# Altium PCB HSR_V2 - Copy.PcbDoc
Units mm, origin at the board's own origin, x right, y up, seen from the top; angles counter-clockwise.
Board outline 140 x 140 mm, 2 copper layers (Top Layer, Bottom Layer), stack 0.533 mm thick; 53 components, 62 nets, 256 pads, 793 vias.
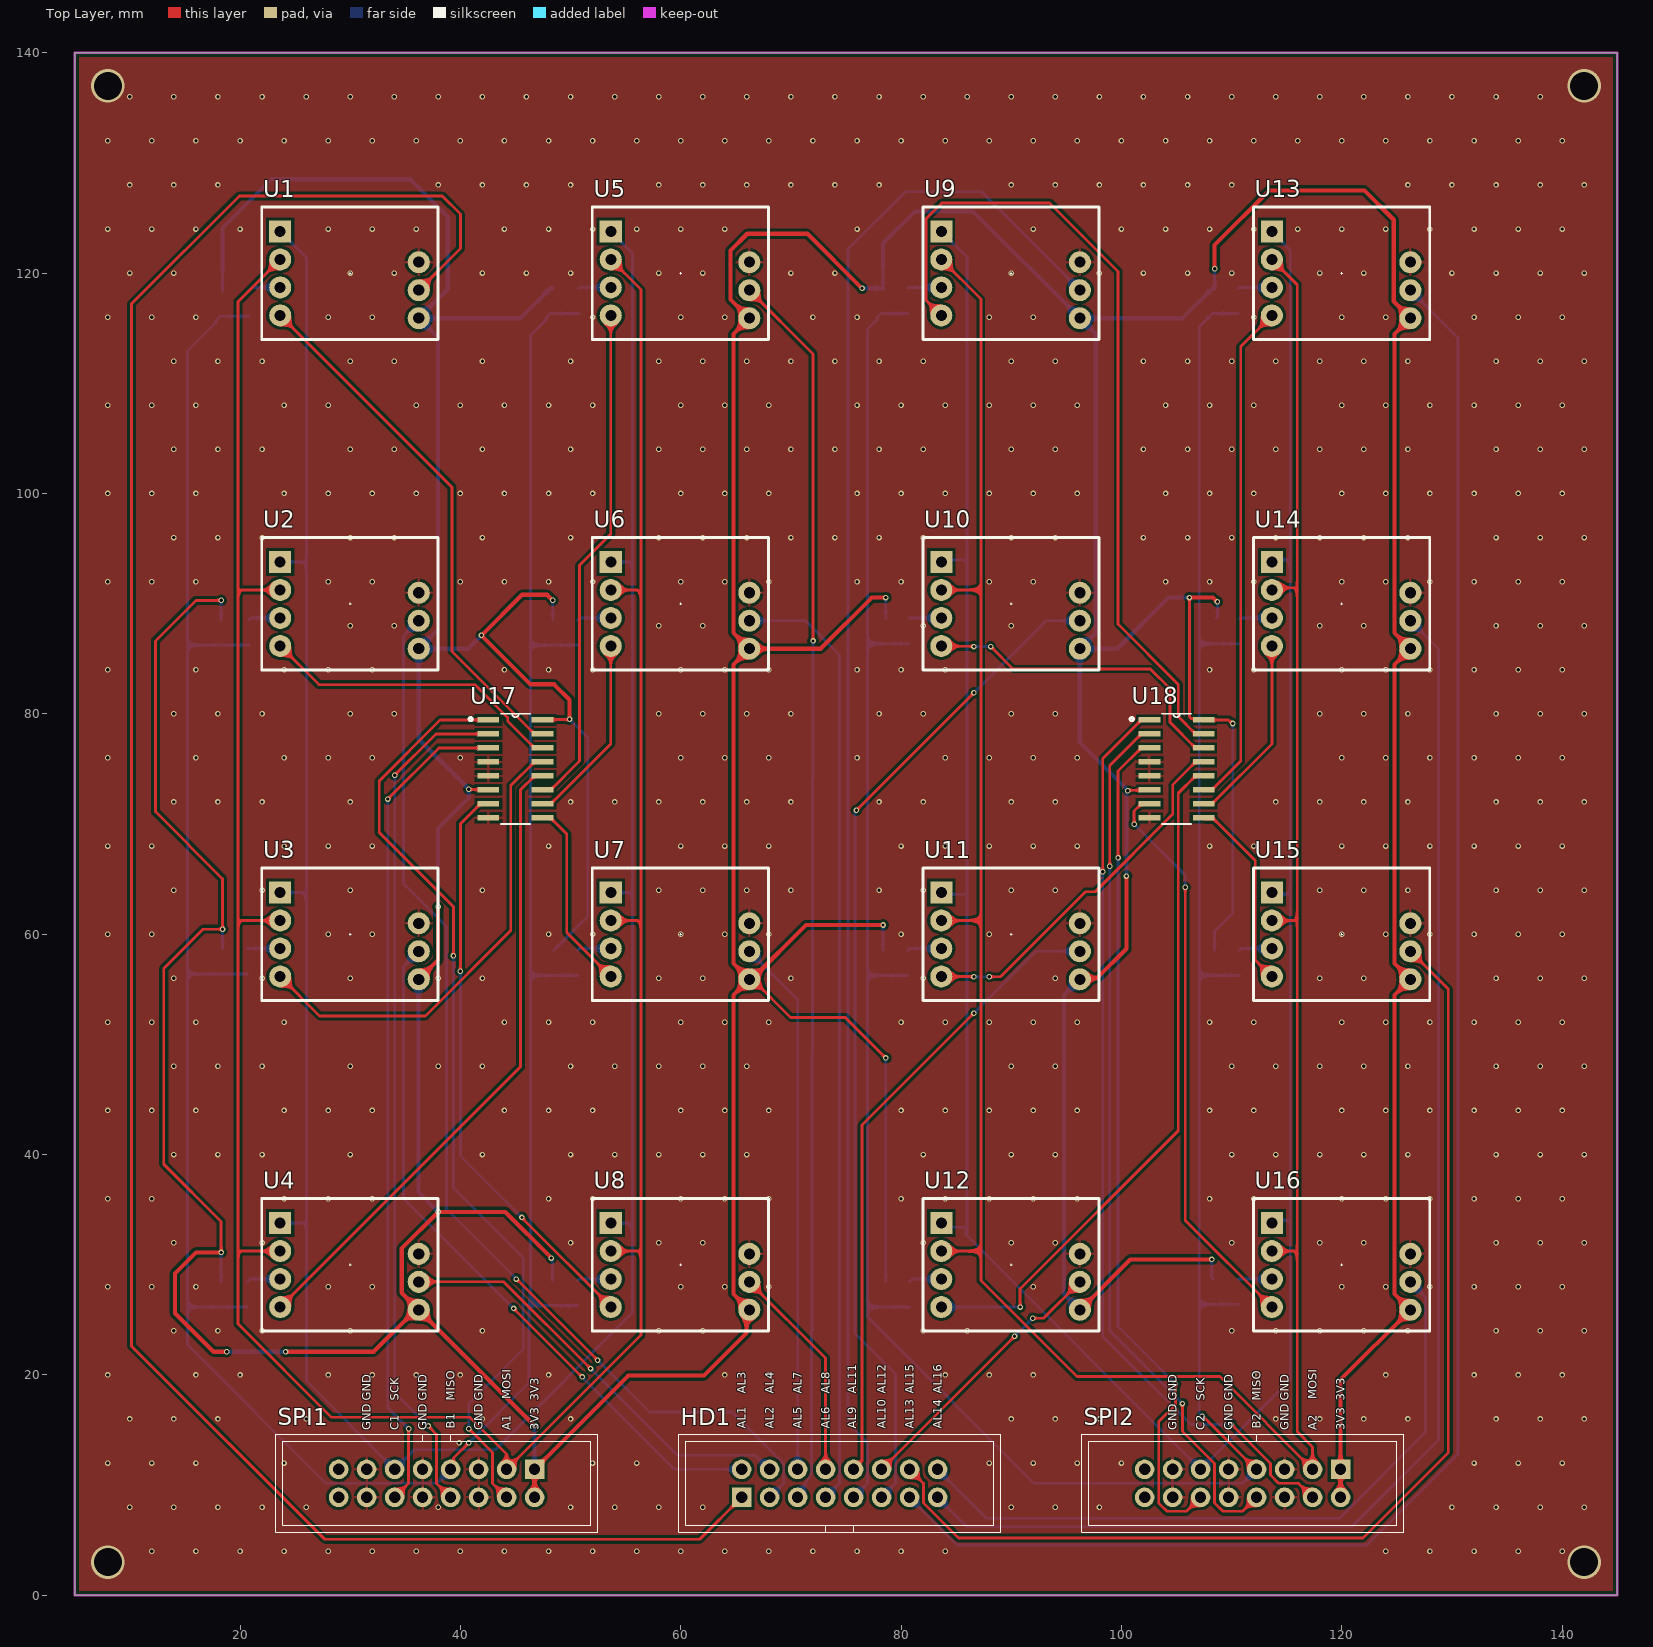
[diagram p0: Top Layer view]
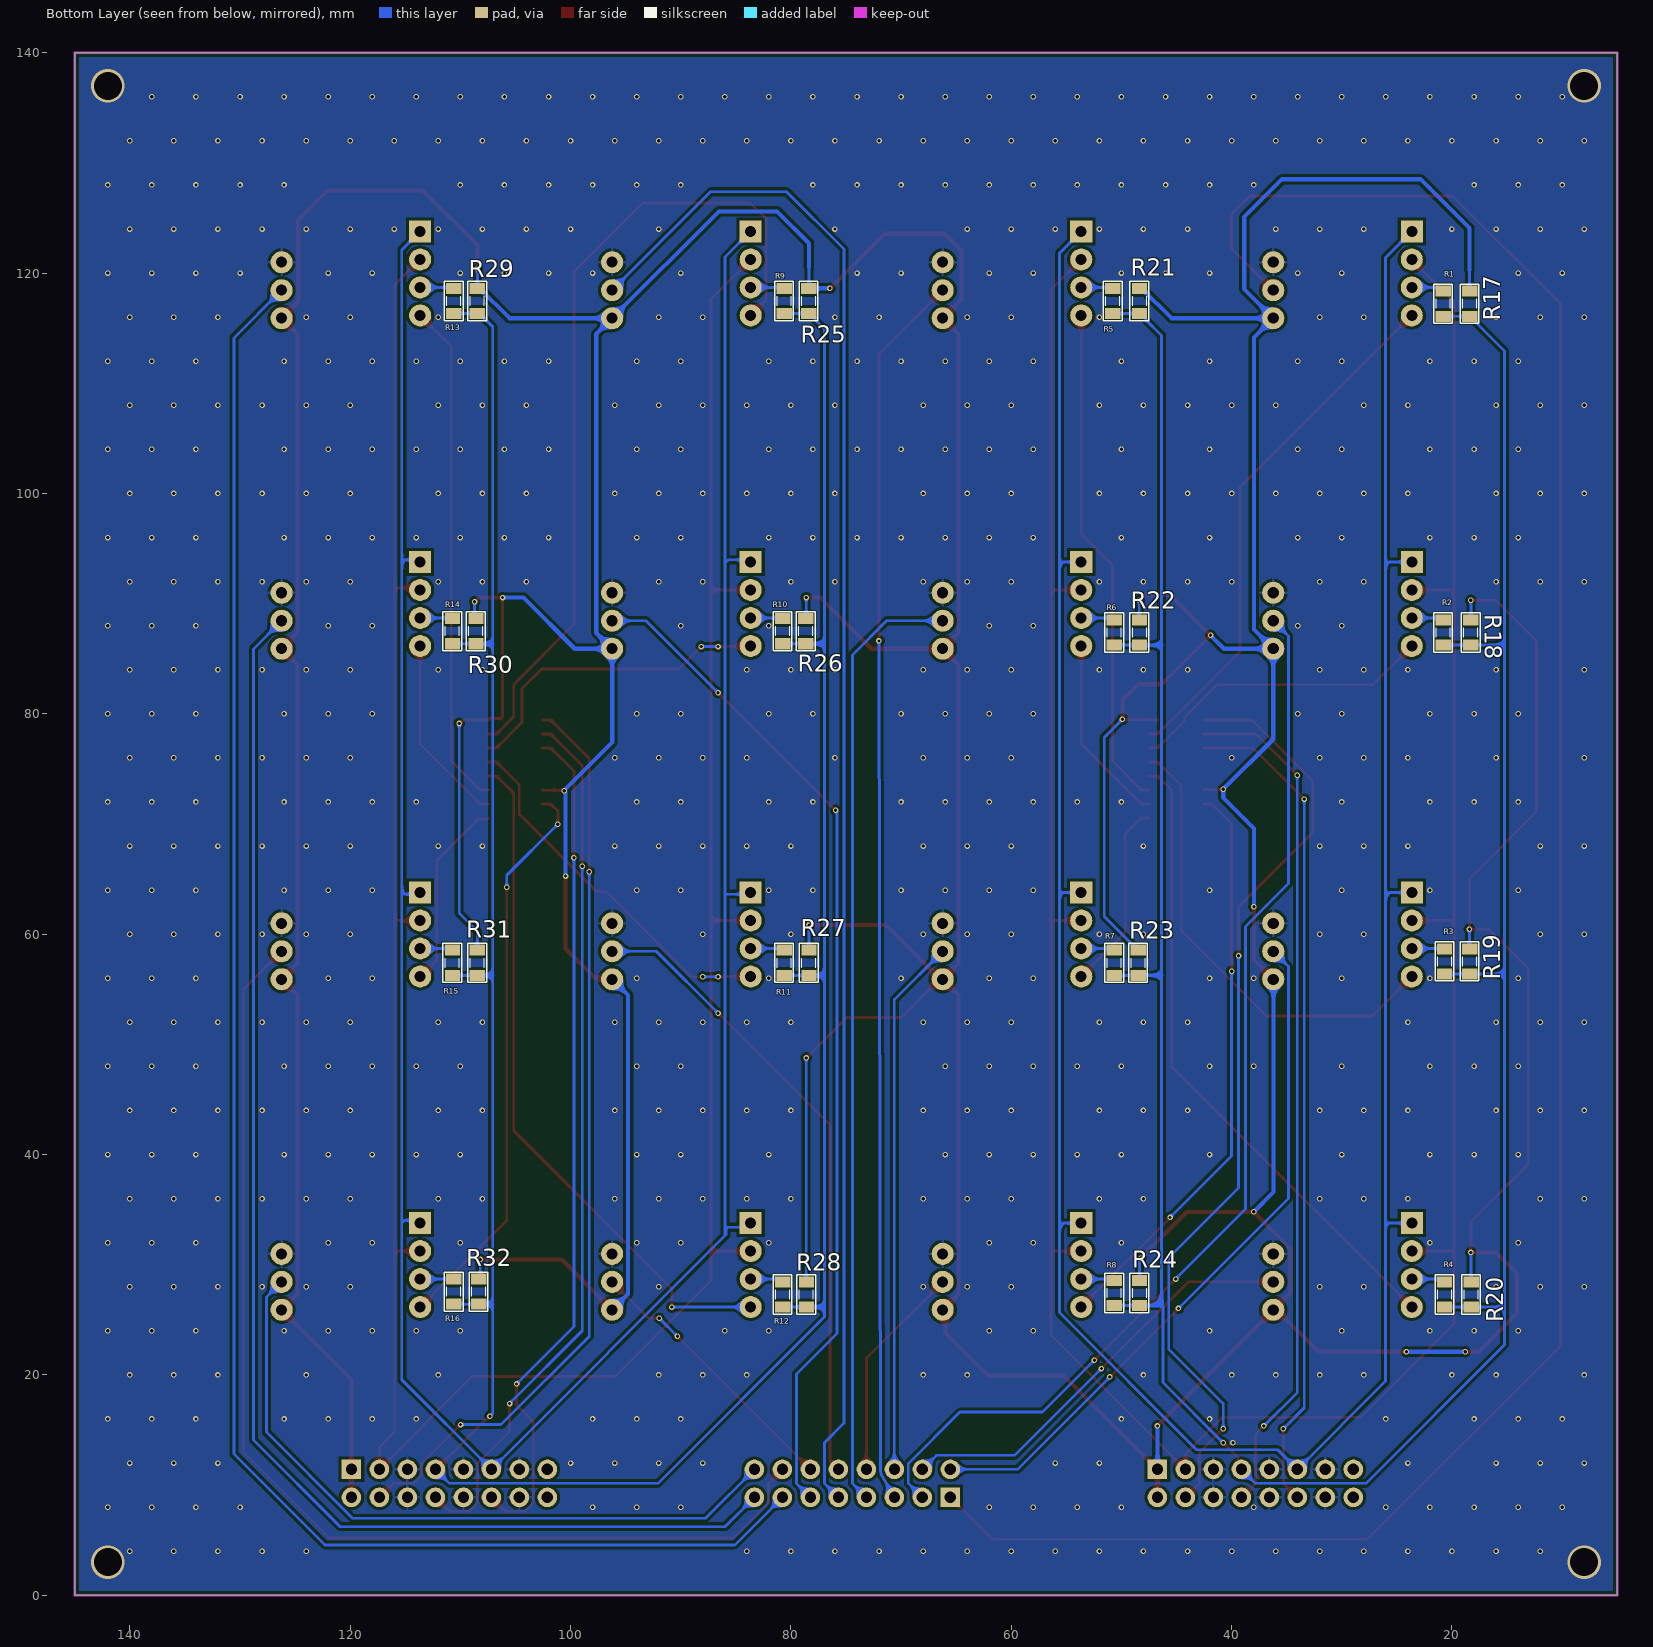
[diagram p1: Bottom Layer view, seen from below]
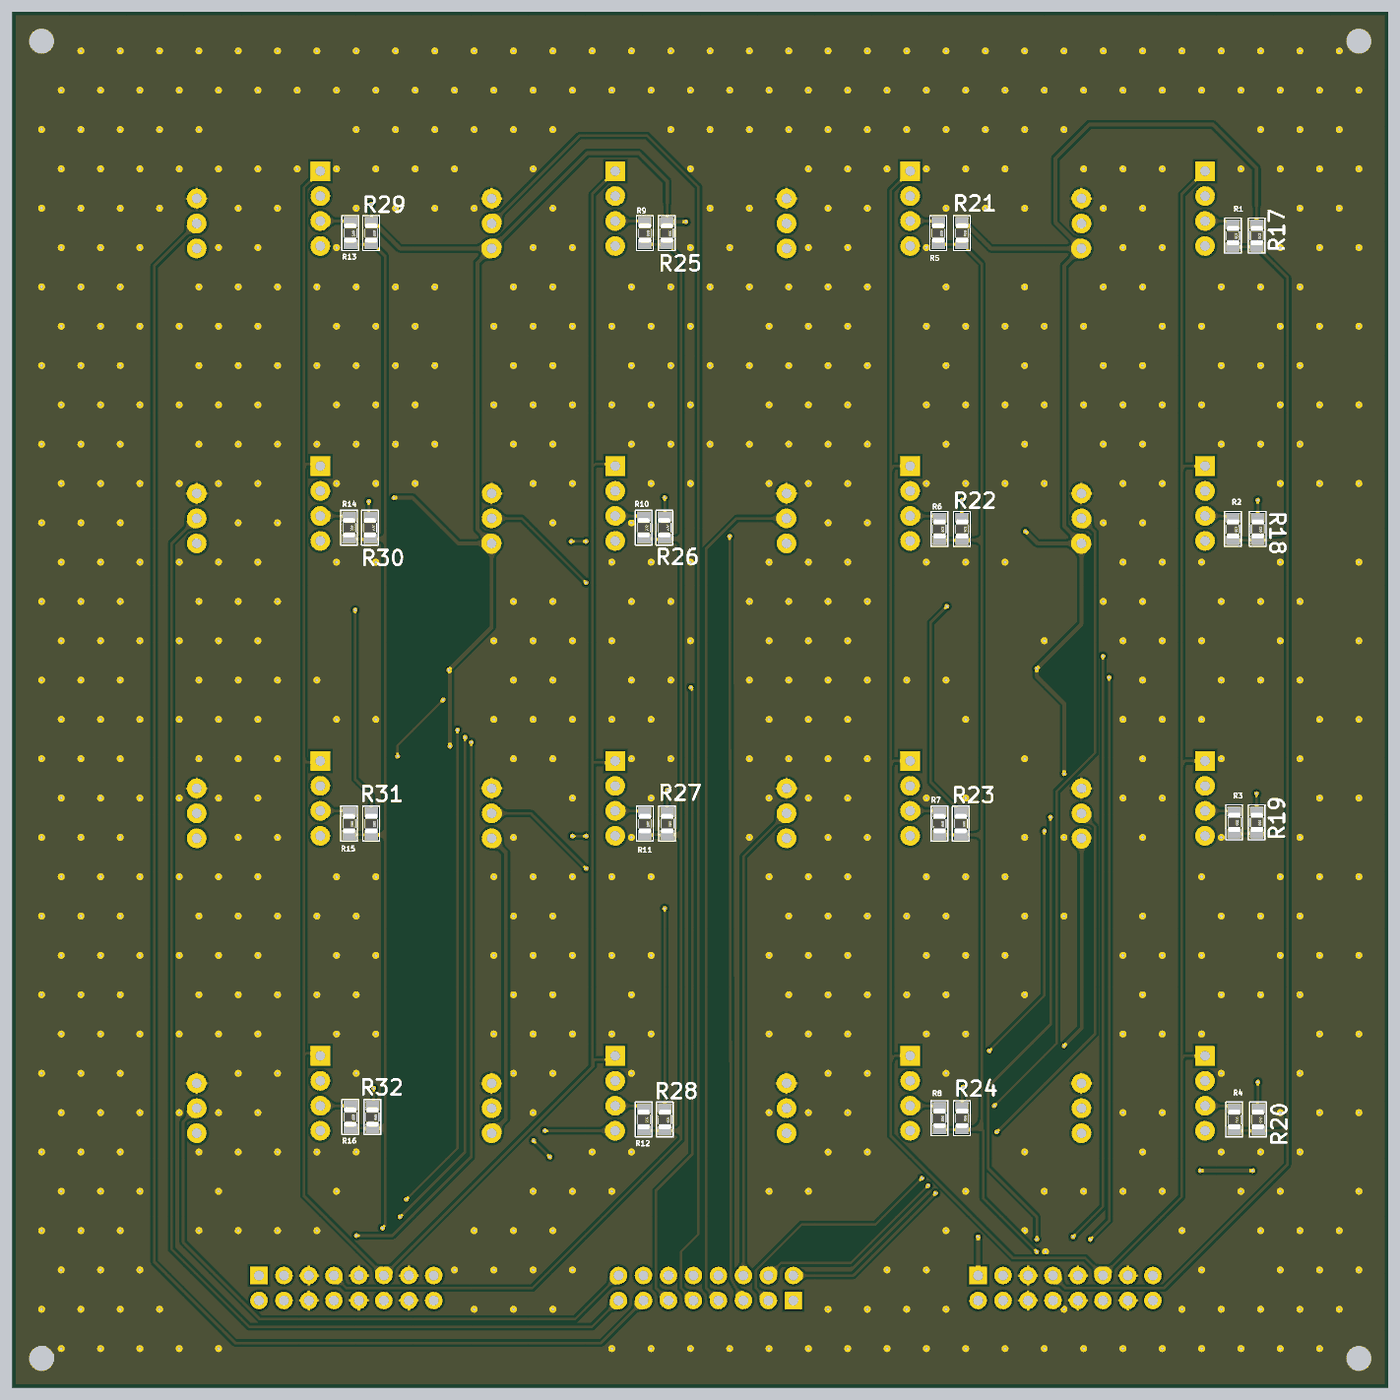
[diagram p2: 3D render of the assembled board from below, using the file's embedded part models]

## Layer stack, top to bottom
Top Solder: solder mask 0.0102, Solder Resist, Dk 3.5
Top Layer: signal copper 0.0356
Dielectric 2: prepreg 0.0711, PP-006, Dk 4.1
Dielectric 1: dielectric 0.32, FR-4, Dk 4.8
Dielectric 3: prepreg 0.0711, PP-006, Dk 4.1
Bottom Layer: signal copper 0.0356
Bottom Solder: solder mask 0.0102, Solder Resist, Dk 3.5

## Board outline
5,0 5,140 145,140 145,0

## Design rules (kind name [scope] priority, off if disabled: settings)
Clearance [All] p1: gap=0.254 ignorepadtopadclearanceinfootprint=FALSE
PolygonConnect [All] p1: connectstyle=Relief reliefconductorwidth=0.254 reliefentries=4 polygonreliefangle="90 Angle" airgapwidth=0.254
RoutingVias [All] p1: holewidth=0.3 width=0.5 viastyle="Through Hole" minholewidth=0.2 minwidth=0.3 maxholewidth=0.711 maxwidth=1.27
SolderMaskExpansion [All] p1: expansion=0.102 istentingtop=FALSE
Width [All] p1: maxlimit=0.762 minlimit=0.254 preferedwidth=0.254 minimp=50.000000 maximp=50.000000 favimp=50.000000
30 further rules are at their usual default settings.

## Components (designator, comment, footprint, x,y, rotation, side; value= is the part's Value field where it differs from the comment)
HD1 "IDC 8X2" IDC16 65.532,8.89 r0 top value="Header 5x2"
R1 "22R" RES-SMD-0805 20.803,117.221 r270 bottom
R2 "22R" RES-SMD-0805 20.803,87.376 r270 bottom
R3 "22R" RES-SMD-0805 20.676,57.531 r270 bottom
R4 "22R" RES-SMD-0805 20.676,27.305 r270 bottom
R5 "22R" RES-SMD-0805 50.775,117.475 r270 bottom
R6 "22R" RES-SMD-0805 50.648,87.376 r270 bottom
R7 "22R" RES-SMD-0805 50.648,57.404 r270 bottom
R8 "22R" RES-SMD-0805 50.648,27.432 r270 bottom
R9 "22R" RES-SMD-0805 80.62,117.475 r270 bottom
R10 "22R" RES-SMD-0805 80.747,87.503 r270 bottom
R11 "22R" RES-SMD-0805 80.62,57.404 r270 bottom
R12 "22R" RES-SMD-0805 80.747,27.305 r270 bottom
R13 "22R" RES-SMD-0805 110.592,117.475 r270 bottom
R14 "22R" RES-SMD-0805 110.719,87.503 r270 bottom
R15 "22R" RES-SMD-0805 110.719,57.404 r270 bottom
R16 "22R" RES-SMD-0805 110.592,27.559 r270 bottom
R17 "10k" RES-SMD-0805 18.39,117.221 r270 bottom
R18 "10k" RES-SMD-0805 18.288,87.376 r270 bottom
R19 "10k" RES-SMD-0805 18.39,57.531 r270 bottom
R20 "10k" RES-SMD-0805 18.263,27.305 r270 bottom
R21 "10k" RES-SMD-0805 48.362,117.475 r270 bottom
R22 "10k" RES-SMD-0805 48.362,87.376 r270 bottom
R23 "10k" RES-SMD-0805 48.489,57.404 r270 bottom
R24 "10k" RES-SMD-0805 48.362,27.432 r270 bottom
R25 "10k" RES-SMD-0805 78.384,117.475 r270 bottom
R26 "10k" RES-SMD-0805 78.638,87.503 r270 bottom
R27 "10k" RES-SMD-0805 78.359,57.404 r270 bottom
R28 "10k" RES-SMD-0805 78.588,27.305 r270 bottom
R29 "10k" RES-SMD-0805 108.458,117.475 r270 bottom
R30 "10k" RES-SMD-0805 108.585,87.503 r270 bottom
R31 "10k" RES-SMD-0805 108.458,57.404 r270 bottom
R32 "10k" RES-SMD-0805 108.331,27.559 r270 bottom
SPI1 "IDC 8X2" IDC16 46.736,11.43 r180 top value="Header 5x2"
SPI2 "IDC 8X2" IDC16 119.888,11.43 r180 top value="Header 5x2"
U1 "TMAG5170_MODULE" "PCBComponent_1 - duplicate" 30,120 r0 top
U2 "TMAG5170_MODULE" "PCBComponent_1 - duplicate" 30,90 r0 top
U3 "TMAG5170_MODULE" "PCBComponent_1 - duplicate" 30,60 r0 top
U4 "TMAG5170_MODULE" "PCBComponent_1 - duplicate" 30,30 r0 top
U5 "TMAG5170_MODULE" "PCBComponent_1 - duplicate" 60,120 r0 top
U6 "TMAG5170_MODULE" "PCBComponent_1 - duplicate" 60,90 r0 top
U7 "TMAG5170_MODULE" "PCBComponent_1 - duplicate" 60,60 r0 top
U8 "TMAG5170_MODULE" "PCBComponent_1 - duplicate" 60,30 r0 top
U9 "TMAG5170_MODULE" "PCBComponent_1 - duplicate" 90,120 r0 top
U10 "TMAG5170_MODULE" "PCBComponent_1 - duplicate" 90,90 r0 top
U11 "TMAG5170_MODULE" "PCBComponent_1 - duplicate" 90,60 r0 top
U12 "TMAG5170_MODULE" "PCBComponent_1 - duplicate" 90,30 r0 top
U13 "TMAG5170_MODULE" "PCBComponent_1 - duplicate" 120,120 r0 top
U14 "TMAG5170_MODULE" "PCBComponent_1 - duplicate" 120,90 r0 top
U15 "TMAG5170_MODULE" "PCBComponent_1 - duplicate" 120,60 r0 top
U16 "TMAG5170_MODULE" "PCBComponent_1 - duplicate" 120,30 r0 top
U17 "SN74LVC138AD" SOIC127P600X175-16N 45,75 r0 top
U18 "SN74LVC138AD" SOIC127P600X175-16N 105,75 r0 top

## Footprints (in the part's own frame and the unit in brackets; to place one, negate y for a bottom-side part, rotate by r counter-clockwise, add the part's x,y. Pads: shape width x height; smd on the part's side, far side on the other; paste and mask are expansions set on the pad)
IDC16 [mil]
  rect 70x70 hole 40: 1(0,0)
  round 70 hole 40: 2(0,100) 3(100,0) 4(100,100) 5(200,0) 6(200,100) 7(300,0) 8(300,100) 9(400,0) 10(400,100) 11(500,0) 12(500,100) 13(600,0) 14(600,100) 15(700,0) 16(700,100)
  silkscreen extent -225,-125 925,225, body extent -225,-125 926,225, height 358
"PCBComponent_1 - duplicate" [mm]
  rect 2x2 hole 1 mask+0.05: 1(-6.35,3.778)
  round 2 hole 1 mask+0.05: 2(-6.35,1.238) 3(-6.35,-1.302) 4(-6.35,-3.842) 5(6.223,-4.092) 6(6.223,-1.552) 7(6.223,0.988)
  silkscreen extent -8.02,-6.03 7.97,6
RES-SMD-0805 [mm]
  rect 1x1.397 smd: 1(-1.143,0) 2(1.143,0)
  silkscreen extent -1.78,-0.86 1.78,0.84, body extent -1,-0.62 1,0.63, height 0.8
SOIC127P600X175-16N [mil]
  rect 78x20 smd: 1(-97,175) 2(-97,125) 3(-97,75) 4(-97,25) 5(-97,-25) 6(-97,-75) 7(-97,-125) 8(-97,-175) 9(97,-175) 10(97,-125) 11(97,-75) 12(97,-25) 13(97,25) 14(97,75) 15(97,125) 16(97,175)
  silkscreen extent -166,-197 52,197, body extent -118,-195 118,195, height 69

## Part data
HD1 SPI1 SPI2: library part "IDC 8x2"
R1 R2 R3 R4 R5 R6 R7 R8 R9 R10 R11 R12 R13 R14 R15 R16 R17 R18 R19 R20 R21 R22 R23 R24 R25 R26 R27 R28 R29 R30 R31 R32: library part "Resistor - SMD", "Resistor SMD", Manufacturer="Generic Components"
U1 U2 U3 U4 U5 U6 U7 U8 U9 U10 U11 U12 U13 U14 U15 U16: "Module TMAG5170 Hall sensor"
U17 U18: "3-Line To 8-Line decoder/Demultiplexer", Package="SOIC-16 Texas Instruments"

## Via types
v1: diameter 0.5, hole 0.3, Top Layer to Bottom Layer, 730 vias
v2: diameter 0.5, hole 0.3, Top Layer to Bottom Layer, tented top, 59 vias
v3: diameter 3.048, hole 2.54, Top Layer to Bottom Layer, tented top, 4 vias

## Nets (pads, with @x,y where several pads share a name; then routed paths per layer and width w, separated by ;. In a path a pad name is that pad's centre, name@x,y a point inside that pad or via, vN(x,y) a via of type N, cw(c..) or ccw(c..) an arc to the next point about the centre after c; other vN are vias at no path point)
3V3: R17.1 R18.1 R19.1 R20.1 R21.1 R22.1 R23.1 R24.1 R25.1 R26.1 R27.1 R28.1 R29.1 R30.1 R31.1 R32.1 SPI1.1 SPI1.2 SPI2.1 SPI2.2 U1.5 U2.5 U3.5 U4.5 U5.5 U6.5 U7.5 U8.5 U9.5 U10.5 U11.5 U12.5 U13.5 U14.5 U15.5 U16.5 U17.6 U17.16 U18.6 U18.16 | length 918.7
  Top Layer w0.254: v2(18.288,31.115) 18.288,33.909 13.081,39.116 13.081,56.896 16.637,60.452 v2(18.415,60.452) 18.415,65.024 12.319,71.12 12.319,86.614 16.002,90.297 v2(18.288,90.297) ; v2(40.767,73.152) 40.795,73.124 42.508,73.124 U17.6 ; U17.16@46.727,79.445 U17.16 47.492,79.474 49.883,79.474 v2(49.911,79.502) ; U7.5@66.52,55.908 69.977,52.451 74.93,52.451 v2(78.613,48.768) ; v2(100.584,73.025) 100.619,73.06 102.501,73.06 U18.6 ; v2(106.172,90.551) 106.172,79.721 106.321,79.572 107.337,79.572 U18.16 109.718,79.445 110.042,79.121 v2(110.109,79.121)
  Top Layer w0.381: v2(18.288,31.115) 16.002,31.115 14.097,29.21 14.097,25.59 17.59,22.098 v2(18.796,22.098) ; v2(24.13,22.098) 32.131,22.098 35.941,25.908 U4.5 ; U3.5 37.973,57.657 v2(37.973,62.484) ; SPI1.2 SPI1.1 55.245,19.939 62.103,19.939 65.973,23.809 65.973,25.657 U8.5 64.779,27.352 64.779,54.463 U7.5 ; v2(46.736,15.367) 46.736,15.381 36.223,25.894 U4.5 ; v2(48.26,30.607) 44.069,34.798 v2(37.991,34.798) 34.671,31.478 34.671,27.46 U4.5 ; v2(48.387,90.297) 47.879,90.805 45.593,90.805 v2(41.91,87.122) 46.355,82.677 48.514,82.677 49.911,81.28 v2(49.911,79.502) ; v2(76.454,118.618) 71.501,123.571 66.04,123.571 64.516,122.047 64.516,117.615 U5.5 64.779,114.463 64.779,87.352 U6.5 ; v2(78.359,60.833) 71.374,60.833 66.449,55.908 U7.5 ; v2(78.613,90.551) 77.343,90.551 72.7,85.908 U6.5 ; U12.5 100.796,30.48 v2(108.204,30.48) ; U11.5 96.328,56.012 97.795,56.012 100.457,58.674 v2(100.457,65.278) ; v2(106.172,90.551) 108.299,90.551 108.68,90.17 v2(108.712,90.17) ; v2(108.458,120.396) 108.458,122.555 113.411,127.508 122.047,127.508 124.714,124.841 124.714,117.417 U13.5 124.779,114.463 124.779,87.352 U14.5 124.779,84.463 124.779,57.352 U15.5 124.779,54.463 124.779,27.352 U16.5 119.888,19.572 SPI2.1 SPI2.2 ; U7.5 64.779,57.352 64.779,84.463 U6.5
  Bottom Layer w0.254: R20.1 18.288,28.473 v2(18.288,31.115) ; R18.1 v2(18.288,90.297) ; R19.1 18.415,58.699 v2(18.415,60.452) ; R17.1 18.415,118.389 18.415,120.269 ; R24.1 v2@48.362,30.439 ; R22.1 48.387,88.544 v2(48.387,90.297) ; R21.1 R21.1@48.387,118.643 ; R23.1 51.562,61.62 51.562,77.851 v2(49.911,79.502) ; R27.1 v2(78.359,60.833) ; 78.359,120.523 78.359,118.643 R25.1 ; R28.1 78.613,28.473 v2(78.613,48.768) ; v2(78.613,90.551) 78.613,88.671 R26.1 ; v2(108.204,30.48) 108.204,28.829 R32.1 ; R31.1 108.458,60.258 110.109,61.909 v2(110.109,79.121) ; R29.1 v2(108.458,120.396) ; R30.1 108.712,88.773 v2(108.712,90.17)
  Bottom Layer w0.381: 18.415,120.269 18.415,124.079 22.86,128.524 35.433,128.524 38.862,125.095 38.862,118.546 U1.5 ; v2(18.796,22.098) v2(24.13,22.098) ; U3.5 36.195,55.879 36.195,36.594 v2(37.991,34.798) ; v2(37.973,62.484) 37.973,69.596 40.767,72.39 v2(40.767,73.152) 36.223,77.696 U2.5 ; v2(41.91,87.122) 40.696,85.908 U2.5 ; SPI1.1 v2(46.736,15.367) ; R21.1 48.163,118.618 45.453,115.908 U1.5 ; v2(76.454,118.618) R25.1 ; 78.359,120.523 78.359,122.713 81.249,125.603 86.528,125.603 U9.5 ; U12.5 94.779,27.352 94.779,54.463 U11.5 ; v2(100.457,65.278) 100.457,72.866 100.584,72.993 v2(100.584,73.025) 96.223,77.386 U10.5 ; v2(106.172,90.551) 104.267,90.551 99.624,85.908 U10.5 ; R29.1 108.26,118.618 105.549,115.908 U9.5 ; U2.5 37.973,87.657 37.973,114.158 U1.5 ; U10.5 97.668,87.352 97.668,114.463 U9.5
A1: SPI1.4 U17.1 | length 86.1
  Top Layer w0.254: v2(39.37,58.039) 39.37,62.484 32.639,69.215 32.639,73.917 38.167,79.445 U17.1 ; v2(40.767,15.113) 42.926,12.954 42.926,10.16 SPI1.4
  Bottom Layer w0.254: v2(39.37,58.039) 39.37,36.957 45.716,30.611 45.716,22.348 40.767,17.399 v2(40.767,15.113)
A2: SPI2.4 U18.1 | length 83.9
  Top Layer w0.254: v2(98.298,65.659) 98.298,75.943 101.8,79.445 U18.1 ; v2(109.982,15.494) 110,15.494 113.538,11.956 113.538,10.904 114.282,10.16 115.334,10.16 116.078,10.16 SPI2.4
  Bottom Layer w0.254: v2(98.298,65.659) 98.298,23.495 106.299,15.494 v2(109.982,15.494)
AL1: HD1.1 U1.6 | length 201.9
  Top Layer w0.254: U1.6 40.005,122.229 40.005,125.349 38.354,127 19.939,127 10.16,117.221 10.16,22.606 27.686,5.08 61.722,5.08 HD1.1
AL2: HD1.3 U2.6 | length 99.3
  Top Layer w0.254: v2(45.085,28.702) v2(52.451,21.336)
  Bottom Layer w0.254: U2.6 34.842,87.067 34.842,64.599 38.735,60.706 38.735,35.052 v2(45.085,28.702) ; v2(52.451,21.336) 57.164,16.623 64.676,16.623 69.342,11.956 69.342,10.16 HD1.3
AL3: HD1.2 U3.6 | length 63.9
  Top Layer w0.254: v2(44.831,26.035) v2(51.054,19.812)
  Bottom Layer w0.254: U3.6 34.842,57.067 34.842,36.024 v2(44.831,26.035) ; v2(51.054,19.812) 59.436,11.43 HD1.2
AL4: HD1.4 U4.6 | length 38.9
  Top Layer w0.254: U4.6 43.942,28.448 v2(51.816,20.574)
  Bottom Layer w0.254: v2(51.816,20.574) 59.69,12.7 66.802,12.7 HD1.4
AL5: HD1.5 U5.6 | length 112.3
  Top Layer w0.254: U5.6 72.009,112.662 v2(72.009,86.614)
  Bottom Layer w0.254: HD1.5 71.712,10.795 ccw(c70.612,11.43) 71.882,11.432 v2(72.009,86.614)
AL6: HD1.7 U6.6 | length 86.5
  Bottom Layer w0.254: U6.6 71.318,88.448 74.422,85.344 74.422,10.16 HD1.7
AL7: HD1.6 U7.6 | length 48.8
  Bottom Layer w0.254: U7.6 70.612,54.059 HD1.6
AL8: HD1.8 U8.6 | length 19.9
  Top Layer w0.254: U8.6 73.152,21.519 HD1.8
AL9: HD1.9 U9.6 | length 141.4
  Bottom Layer w0.254: HD1.9 76.962,10.16 76.962,13.843 75.184,15.621 75.184,122.174 80.391,127.381 87.29,127.381 U9.6
AL10: HD1.11 U10.6 | length 91.9
  Top Layer w0.254: v2(75.946,71.247) 86.61,81.911 v2(86.61,81.915)
  Bottom Layer w0.254: v2(75.946,71.247) 75.946,71.18 75.819,71.053 75.819,23.749 79.502,20.066 79.502,10.16 HD1.11 ; v2(86.61,81.915) 93.143,88.448 U10.6
AL11: HD1.10 U11.6 | length 57.9
  Top Layer w0.254: HD1.10 75.692,11.492 76.454,12.254 76.454,42.676 v2(86.61,52.832)
  Bottom Layer w0.254: v2(86.61,52.832) 92.226,58.448 U11.6
AL12: HD1.12 U12.6 | length 25
  Top Layer w0.254: HD1.12 v2(90.297,23.495) ; v2(91.948,25.146) 92.922,25.146 U12.6
  Bottom Layer w0.254: v2(90.297,23.495) v2(91.948,25.146)
AL13: HD1.13 U13.6 | length 162.4
  Bottom Layer w0.254: HD1.13 85.09,4.572 122.301,4.572 130.556,12.827 130.556,114.115 U13.6
AL14: HD1.15 U14.6 | length 125.2
  Bottom Layer w0.254: HD1.15 85.979,6.223 120.904,6.223 128.778,14.097 128.778,85.893 U14.6
AL15: HD1.14 U15.6 | length 102.7
  Top Layer w0.254: HD1.14 82.042,10.16 82.042,8.364 85.199,5.207 121.92,5.207 129.667,12.954 129.667,55.004 U15.6
AL16: HD1.16 U16.6 | length 63.6
  Bottom Layer w0.254: HD1.16 87.757,6.985 119.779,6.985 127.604,14.81 127.604,27.067 U16.6
B1: SPI1.8 U17.2 | length 77.7
  Top Layer w0.254: v2(34.036,74.422) 37.789,78.175 U17.2 ; v2(37.084,15.367) 37.846,14.605 37.846,10.16 SPI1.8
  Bottom Layer w0.254: v2(34.036,74.422) 34.036,18.415 v2(37.084,15.367)
B2: SPI2.8 U18.2 | length 80.3
  Top Layer w0.254: v2(98.933,66.167) 98.933,75.308 101.8,78.175 U18.2 ; v2(105.537,17.399) 105.537,14.877 108.458,11.956 108.458,8.364 109.202,7.62 110.998,7.62 SPI2.8
  Bottom Layer w0.254: v2(98.933,66.167) 98.933,24.003 v2(105.537,17.399)
C1: SPI1.12 U17.3 | length 75.7
  Top Layer w0.254: v2(33.405,72.263) 38.047,76.905 U17.3 ; SPI1.12 35.306,10.16 v2(35.306,15.113)
  Bottom Layer w0.254: v2(33.405,72.263) 33.405,17.014 v2(35.306,15.113)
C2: SPI2.12 U18.3 | length 77.6
  Top Layer w0.254: v2(99.695,66.929) 99.695,74.8 101.8,76.905 U18.3 ; v2(104.902,19.177) 104.902,17.272 103.378,15.748 103.378,11.437 ; SPI2.12 105.918,7.62 104.122,7.62 103.452,8.29 103.378,8.364 103.378,8.883 ; 103.378,8.883 cw(c104.648,8.89) 103.378,8.897 ; 103.378,8.883 cw(c104.648,8.89) 103.378,8.897 ; 103.378,8.897 103.378,11.423 ; 103.378,11.423 cw(c104.648,11.43) 103.378,11.437 ; 103.378,11.423 cw(c104.648,11.43) 103.378,11.437
  Bottom Layer w0.254: v2(99.695,66.929) 99.695,24.384 v2(104.902,19.177)
GND: SPI1.5 SPI1.6 SPI1.9 SPI1.10 SPI1.13 SPI1.14 SPI2.5 SPI2.6 SPI2.9 SPI2.10 SPI2.13 SPI2.14 U1.7 U2.7 U3.7 U4.7 U5.7 U6.7 U7.7 U8.7 U9.7 U10.7 U11.7 U12.7 U13.7 U14.7 U15.7 U16.7 U17.4 U17.5 U17.8 U18.4 U18.5 U18.8
  other v1: 12,4 16,4 20,4 24,4 28,4 32,4 36,4 40,4 44,4 48,4 52,4 56,4 60,4 64,4 68,4 72,4 76,4 80,4 84,4 124,4 128,4 132,4 136,4 140,4 10,8 14,8 18,8 22,8 26,8 38,8 50,8 54,8 58,8 62,8 90,8 94,8 98,8 130,8 134,8 138,8 142,8 8,12 12,12 16,12 24,12 52,12 56,12 88,12 92,12 96,12 100,12 132,12 136,12 140,12 10,16 14,16 18,16 26,16 42,16 50,16 90,16 94,16 98,16 114,16 118,16 122,16 126,16 134,16 138,16 142,16 8,20 16,20 20,20 28,20 32,20 36,20 40,20 48,20 64,20 68,20 84,20 88,20 92,20 112,20 124,20 132,20 136,20 140,20 14,24 18,24 22,24 30,24 42,24 58,24 62,24 82,24 86,24 110,24 114,24 118,24 122,24 126,24 134,24 138,24 142,24 8,28 12,28 16,28 28,28 32,28 60,28 64,28 68,28 92,28 120,28 124,28 128,28 132,28 136,28 140,28 14,32 22,32 50,32 58,32 62,32 82,32 90,32 94,32 110,32 118,32 122,32 134,32 138,32 142,32 8,36 12,36 24,36 28,36 32,36 48,36 52,36 60,36 64,36 68,36 80,36 84,36 88,36 92,36 96,36 108,36 112,36 120,36 124,36 128,36 132,36 136,36 140,36 14,40 18,40 22,40 30,40 42,40 50,40 54,40 58,40 62,40 66,40 82,40 90,40 94,40 110,40 114,40 118,40 122,40 126,40 134,40 138,40 142,40 8,44 12,44 16,44 24,44 28,44 32,44 44,44 48,44 52,44 60,44 64,44 68,44 80,44 84,44 88,44 92,44 96,44 108,44 112,44 120,44 124,44 128,44 132,44 136,44 140,44 14,48 18,48 22,48 30,48 38,48 42,48 50,48 54,48 58,48 62,48 66,48 90,48 94,48 110,48 114,48 118,48 122,48 126,48 134,48 138,48 142,48 8,52 12,52 16,52 24,52 44,52 48,52 52,52 60,52 64,52 68,52 80,52 84,52 88,52 92,52 96,52 108,52 112,52 120,52 124,52 128,52 132,52 136,52 140,52 14,56 22,56 30,56 38,56 42,56 58,56 62,56 70,56 82,56 94,56 118,56 122,56 134,56 138,56 142,56 8,60 12,60 28,60 32,60 48,60 52,60 60,60 64,60 68,60 80,60 88,60 120,60 124,60 128,60 132,60 136,60 140,60 14,64 22,64 30,64 42,64 58,64 62,64 66,64 70,64 78,64 82,64 90,64 94,64 118,64 122,64 126,64 134,64 138,64 142,64 8,68 12,68 24,68 28,68 32,68 48,68 60,68 64,68 68,68 80,68 84,68 88,68 92,68 96,68 108,68 112,68 120,68 124,68 128,68 132,68 136,68 140,68 14,72 18,72 22,72 30,72 50,72 54,72 58,72 62,72 66,72 70,72 78,72 82,72 90,72 94,72 114,72 118,72 122,72 126,72 134,72 138,72 142,72 8,76 16,76 24,76 28,76 32,76 40,76 60,76 64,76 68,76 76,76 84,76 88,76 92,76 96,76 120,76 124,76 128,76 132,76 136,76 140,76 14,80 18,80 22,80 30,80 34,80 58,80 62,80 66,80 70,80 78,80 82,80 90,80 94,80 118,80 122,80 126,80 134,80 138,80 142,80 8,84 16,84 24,84 28,84 32,84 44,84 48,84 52,84 60,84 64,84 68,84 76,84 80,84 84,84 108,84 112,84 120,84 124,84 128,84 132,84 136,84 140,84 30,88 34,88 58,88 62,88 82,88 90,88 118,88 122,88 134,88 138,88 142,88 8,92 12,92 16,92 28,92 32,92 40,92 44,92 48,92 52,92 60,92 64,92 68,92 76,92 80,92 88,92 92,92 104,92 108,92 112,92 120,92 124,92 128,92 132,92 136,92 140,92 14,96 18,96 22,96 30,96 34,96 42,96 50,96 58,96 62,96 66,96 70,96 74,96 78,96 82,96 90,96 94,96 102,96 106,96 110,96 114,96 118,96 122,96 126,96 134,96 138,96 142,96 8,100 12,100 16,100 24,100 28,100 32,100 36,100 40,100 44,100 48,100 52,100 60,100 64,100 68,100 76,100 80,100 84,100 88,100 92,100 96,100 104,100 108,100 112,100 120,100 124,100 128,100 132,100 136,100 140,100 14,104 18,104 22,104 30,104 34,104 42,104 50,104 58,104 62,104 66,104 70,104 74,104 78,104 82,104 90,104 94,104 102,104 106,104 110,104 114,104 118,104 122,104 126,104 134,104 138,104 142,104 8,108 12,108 16,108 24,108 28,108 36,108 40,108 44,108 48,108 52,108 60,108 64,108 68,108 76,108 80,108 84,108 88,108 92,108 96,108 104,108 108,108 112,108 120,108 124,108 128,108 132,108 136,108 140,108 14,112 18,112 22,112 30,112 34,112 42,112 50,112 58,112 62,112 66,112 70,112 74,112 78,112 82,112 90,112 94,112 102,112 106,112 110,112 114,112 118,112 122,112 126,112 134,112 138,112 142,112 8,116 12,116 16,116 28,116 32,116 52,116 60,116 64,116 72,116 76,116 88,116 92,116 112,116 120,116 124,116 132,116 136,116 140,116 10,120 14,120 30,120 34,120 42,120 46,120 50,120 58,120 62,120 70,120 74,120 90,120 98,120 102,120 106,120 110,120 118,120 122,120 130,120 134,120 138,120 142,120 8,124 12,124 16,124 20,124 28,124 32,124 36,124 44,124 48,124 52,124 56,124 60,124 64,124 76,124 92,124 100,124 104,124 108,124 112,124 116,124 120,124 124,124 128,124 132,124 136,124 140,124 10,128 14,128 18,128 38,128 42,128 46,128 50,128 54,128 58,128 62,128 66,128 70,128 74,128 78,128 90,128 94,128 98,128 102,128 106,128 110,128 126,128 130,128 134,128 138,128 142,128 8,132 12,132 16,132 20,132 24,132 28,132 32,132 36,132 40,132 44,132 48,132 52,132 56,132 60,132 64,132 68,132 72,132 76,132 80,132 84,132 88,132 92,132 96,132 100,132 104,132 108,132 112,132 116,132 120,132 124,132 128,132 132,132 136,132 140,132 10,136 14,136 18,136 22,136 26,136 30,136 34,136 38,136 42,136 46,136 50,136 54,136 58,136 62,136 66,136 70,136 74,136 78,136 82,136 86,136 90,136 94,136 98,136 102,136 106,136 110,136 114,136 118,136 122,136 126,136 130,136 134,136 138,136
  other v2: 39.878,13.847
  other v3: 8,3 142,3 8,137 142,137
NetR1_1: R1.1 U1.3 | length 3
  Bottom Layer w0.254: R1.1 21.136,118.698 U1.3
NetR2_1: R2.1 U2.3 | length 2.9
  Bottom Layer w0.254: R2.1 20.981,88.698 U2.3
NetR3_1: R3.1 U3.3 | length 3
  Bottom Layer w0.254: R3.1 20.699,58.698 U3.3
NetR4_1: R4.1 U4.3 | length 3.1
  Bottom Layer w0.254: R4.1 20.925,28.698 U4.3
NetR5_1: R5.1 U5.3 | length 2.9
  Bottom Layer w0.254: R5.1 50.854,118.698 U5.3
NetR6_1: R6.1 U6.3 | length 3.1
  Bottom Layer w0.254: R6.1 50.826,88.698 U6.3
NetR7_1: R7.1 U7.3 | length 3.1
  Bottom Layer w0.254: R7.1 50.798,58.698 U7.3
NetR8_1: R8.1 U8.3 | length 3.1
  Top Layer w0.254: U8.3@53.648,28.7 U8.3
  Bottom Layer w0.254: R8.1 50.77,28.698 U8.3
NetR9_1: R9.1 U9.3 | length 3.1
  Top Layer w0.254: U9.3@83.627,118.721 U9.3
  Bottom Layer w0.254: R9.1 80.699,118.698 U9.3
NetR10_1: R10.1 U10.3 | length 3
  Top Layer w0.254: U10.3@83.624,88.672 U10.3
  Bottom Layer w0.254: R10.1 80.798,88.698 U10.3
NetR11_1: R11.1 U11.3 | length 3.1
  Bottom Layer w0.254: R11.1 80.77,58.698 U11.3
NetR12_1: R12.1 U12.3 | length 3
  Bottom Layer w0.254: R12.1 80.996,28.698 U12.3
NetR13_1: R13.1 U13.3 | length 3.1
  Top Layer w0.254: U13.3@113.61,118.658 U13.3
  Bottom Layer w0.254: R13.1 110.671,118.698 U13.3
NetR14_1: R14.1 U14.3 | length 3
  Top Layer w0.254: U14.3@113.613,88.735 U14.3
  Bottom Layer w0.254: R14.1 110.77,88.698 U14.3
NetR15_1: R15.1 U15.3 | length 3
  Top Layer w0.254: U15.3@113.638,58.686 U15.3
  Bottom Layer w0.254: R15.1 110.869,58.698 U15.3
NetR16_1: R16.1 U16.3 | length 3.1
  Bottom Layer w0.254: R16.1 110.596,28.698 U16.3
SENS1: U1.4 U17.15 | length 48.3
  Top Layer w0.254: U1.4 39.243,100.565 39.243,85.659 46.727,78.175 U17.15
SENS2: U2.4 U17.14 | length 27.8
  Top Layer w0.254: U2.4 27.161,82.647 41.305,82.647 44.294,79.658 44.294,79.338 46.727,76.905 U17.14
SENS3: U3.4 U17.13 | length 42.6
  Top Layer w0.254: U3.4 27.23,52.578 36.83,52.578 44.577,60.325 44.577,73.485 46.727,75.635 U17.13
SENS4: U4.4 U17.12 | length 58.5
  Top Layer w0.254: U4.4 45.466,47.973 45.466,73.104 46.727,74.365 U17.12
SENS5: U5.4 U17.11 | length 46.1
  Top Layer w0.254: U17.11 48.2,73.095 50.822,75.716 50.822,93.488 53.65,96.317 U5.4
SENS6: U6.4 U17.10 | length 17.3
  Top Layer w0.254: U17.10 48.2,71.825 53.65,77.275 U6.4
SENS7: U7.4 U17.9 | length 17.4
  Top Layer w0.254: U17.9 48.2,70.555 49.657,69.098 49.657,60.151 U7.4
SENS8: U8.4 U17.7 | length 52.8
  Top Layer w0.254: v2(40.001,56.642) 40.001,70.026 41.8,71.825 U17.7 ; v2(45.593,34.29) 45.593,34.253 53.65,26.195 U8.4
  Bottom Layer w0.254: v2(40.001,56.642) 40.001,39.882 v2(45.593,34.29)
SENS9: U9.4 U18.15 | length 75.6
  Top Layer w0.254: U9.4 82.269,117.539 82.269,124.936 83.699,126.365 93.472,126.365 99.695,120.142 99.695,88.138 105.156,82.677 105.156,79.746 106.727,78.175 U18.15
SENS10: U10.4 U18.14 | length 29.4
  Top Layer w0.254: U10.4 83.676,86.132 86.588,86.132 v2(86.614,86.106) ; v2(88.138,86.106) 90.17,84.074 102.616,84.074 104.394,82.296 104.394,79.238 106.727,76.905 U18.14
  Bottom Layer w0.254: v2(86.614,86.106) v2(88.138,86.106)
SENS11: U11.4 U18.13 | length 33.5
  Top Layer w0.254: U11.4 83.656,56.152 86.592,56.152 v2(86.61,56.134) ; v2(88.011,56.134) 89.027,56.134 96.746,63.853 97.618,63.853 104.648,70.883 104.648,73.556 106.727,75.635 U18.13
  Bottom Layer w0.254: v2(86.61,56.134) v2(88.011,56.134)
SENS12: U12.4 U18.12 | length 62.7
  Top Layer w0.254: v2(90.805,26.162) 90.805,27.813 105.156,42.164 105.156,72.794 106.727,74.365 U18.12
  Bottom Layer w0.254: U12.4 83.652,26.16 90.803,26.16 v2(90.805,26.162)
SENS13: U13.4 U18.11 | length 46.1
  Top Layer w0.254: U18.11 108.2,73.095 110.822,75.716 110.822,113.329 U13.4
SENS14: U14.4 U18.10 | length 17.3
  Top Layer w0.254: U18.10 108.2,71.825 113.65,77.275 U14.4
SENS15: U15.4 U18.9 | length 17.4
  Top Layer w0.254: U18.9 107.591,70.428 108.388,70.428 112.141,66.675 112.141,57.667 U15.4
SENS16: U16.4 U18.7 | length 51.9
  Top Layer w0.254: v2(101.151,69.987) 101.151,71.177 101.8,71.825 U18.7 ; v2(105.791,64.262) 105.787,64.258 105.787,34.021 U16.4
  Bottom Layer w0.254: v2(101.151,69.987) 105.791,65.347 v2(105.791,64.262)
SPI1_MISO: R1.2 R2.2 R3.2 R4.2 R5.2 R6.2 R7.2 R8.2 R17.2 R18.2 R19.2 R20.2 R21.2 R22.2 R23.2 R24.2 SPI1.7 | length 267.4
  Top Layer w0.254: SPI1.7 39.379,11.693 39.379,12.455 v2(40.767,13.843)
  Bottom Layer w0.254: R4.2 R20.2 15.24,26.162 ; R3.2 R19.2 15.24,56.388 ; R2.2 R18.2 15.24,86.233 ; R1.2 R17.2 18.191,116.078 17.818,115.705 17.818,115.507 15.24,112.928 15.24,86.233 ; SPI1.7 37.846,10.16 34.562,10.16 27.813,10.16 15.24,22.733 15.24,26.162 ; v2(40.767,13.843) 46.224,19.3 46.224,26.158 46.355,26.289 ; R8.2 R24.2 46.355,26.289 ; R7.2 R23.2 46.355,56.261 ; R6.2 R22.2 46.355,86.233 ; R5.2 R21.2 48.163,116.332 47.79,115.959 47.79,115.761 46.355,114.325 46.355,86.233 ; 15.24,26.162 15.24,56.388 ; 15.24,56.388 15.24,86.233 ; 46.355,26.289 46.355,56.261 ; 46.355,56.261 46.355,86.233
SPI1_MOSI: SPI1.3 U1.2 U2.2 U3.2 U4.2 U5.2 U6.2 U7.2 U8.2 | length 265.4
  Top Layer w0.254: U4.2 20.062,31.238 19.812,30.988 ; U3.2 20.09,61.238 19.812,60.96 ; U2.2 20.118,91.238 19.812,90.932 ; U1.2 19.812,117.4 19.812,90.932 ; U8.2 56.138,31.238 56.388,30.988 ; U7.2 56.11,61.238 56.388,60.96 ; U6.2 56.082,91.238 56.388,90.932 ; U5.2 56.388,118.5 56.388,91.186 ; 56.336,91.238 56.388,91.186 ; 56.364,61.238 56.388,61.214 ; 19.812,30.988 19.812,24.638 28.302,16.148 40.875,16.148 44.196,12.827 SPI1.3 48.771,16.005 56.388,23.622 56.388,30.988 ; 19.812,30.988 19.812,60.96 ; 19.812,60.96 19.812,90.932 ; 56.388,30.988 56.388,60.96 ; 56.388,60.96 56.388,61.214 ; 56.388,61.214 56.388,90.932 ; 56.388,90.932 56.388,91.186
SPI1_SCK: SPI1.11 U1.1 U2.1 U3.1 U4.1 U5.1 U6.1 U7.1 U8.1 | length 258.2
  Bottom Layer w0.254: U3.1 25.678,63.778 26.035,63.421 ; U2.1 25.729,93.778 26.035,93.472 ; U1.1 26.035,121.393 26.035,93.472 ; U4.1@24.523,32.905 U4.1 25.785,33.778 26.035,33.528 ; U8.1 55.249,33.778 55.626,33.401 ; U7.1 55.348,63.778 55.626,63.5 ; U6.1 55.32,93.778 55.626,93.472 ; U5.1 55.626,121.802 55.626,93.472 ; 26.035,33.528 26.035,63.421 ; 26.035,33.528 26.035,19.431 SPI1.11 35.818,13.212 43.184,13.212 55.626,25.654 55.626,33.401 ; 26.035,63.421 26.035,93.472 ; 55.626,33.401 55.626,63.5 ; 55.626,63.5 55.626,93.472
SPI2_MISO: R9.2 R10.2 R11.2 R12.2 R13.2 R14.2 R15.2 R16.2 R25.2 R26.2 R27.2 R28.2 R29.2 R30.2 R31.2 R32.2 SPI2.7 | length 268
  Top Layer w0.254: v2@107.379,16.256 SPI2.7@112.204,11.43
  Bottom Layer w0.254: R11.2 R27.2 76.962,56.261 ; R9.2 R25.2 78.186,116.332 77.813,115.959 77.813,115.761 76.962,114.91 76.962,86.36 ; R12.2 R28.2 76.962,26.162 ; R10.2 R26.2 76.962,86.36 ; v2(107.315,16.256) 107.315,16.274 107.061,16.528 107.061,26.416 ; R16.2 R32.2 107.061,26.416 ; R13.2 R29.2 108.26,116.332 107.061,115.134 107.061,86.36 ; R15.2 R31.2 107.061,56.261 ; R14.2 R30.2 107.061,86.36 ; SPI2.7 110.998,10.16 107.714,10.16 92.075,10.16 76.962,25.273 76.962,26.162 ; 76.962,26.162 76.962,56.261 ; 76.962,56.261 76.962,86.36 ; 107.061,26.416 107.061,56.261 ; 107.061,56.261 107.061,86.36
SPI2_MOSI: SPI2.3 U9.2 U10.2 U11.2 U12.2 U13.2 U14.2 U15.2 U16.2 | length 260.8
  Top Layer w0.254: U12.2 87.241,31.238 ; U11.2 87.241,61.238 ; U10.2 87.245,91.238 ; U9.2 87.245,117.643 87.245,91.238 ; U16.2 115.701,31.238 115.951,30.988 ; U15.2 115.721,61.238 115.951,61.468 ; U14.2 113.853,91.44 115.697,91.44 115.951,91.186 ; U13.2 115.951,118.937 115.951,91.186 ; 87.241,31.238 87.241,28.583 95.982,19.842 108.936,19.842 SPI2.3 117.348,13.462 115.951,14.859 115.951,30.988 ; 87.241,31.238 87.241,61.238 ; 87.241,61.238 87.241,85.841 87.245,85.845 87.245,91.238 ; 115.951,30.988 115.951,61.468 ; 115.951,61.468 115.951,91.186
SPI2_SCK: SPI2.11 U9.1 U10.1 U11.1 U12.1 U13.1 U14.1 U15.1 U16.1 | length 252.2
  Bottom Layer w0.254: U12.1 84.027,33.401 85.729,33.401 85.979,33.151 ; U11.1 83.801,63.627 85.955,63.627 85.979,63.651 ; U10.1 83.853,93.98 85.673,93.98 85.979,93.674 ; U9.1 85.979,121.449 85.979,93.778 85.979,93.674 ; 85.876,33.151 85.876,32.742 85.979,32.639 ; U16.1 113.908,34.036 115.058,34.036 115.316,33.778 ; U15.1 113.801,63.627 115.062,63.627 115.316,63.881 ; U14.1 113.853,93.98 115.062,93.98 115.316,93.726 ; U13.1 115.316,122.112 115.316,93.726 ; 85.979,32.639 85.979,32.742 85.979,33.151 ; 85.979,32.639 SPI2.11 115.316,19.558 115.316,33.655 115.316,33.778 ; 85.979,33.151 85.979,63.627 85.979,63.778 85.979,63.881 85.979,93.674 ; 115.316,33.778 115.316,63.778 115.316,63.881 ; 115.316,63.881 115.316,93.726
pads on no net: SPI1.15 SPI1.16 SPI2.15 SPI2.16

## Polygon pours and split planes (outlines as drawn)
GND on Top Layer "GND_L01_P004" (solid, remove dead copper, pour order 4): 1.397,143.764 1.651,143.51 149.86,143.51 149.86,1.143 151.003,0 0,0 0,141.605 2.159,143.764
GND on Bottom Layer "GND_L02_P007" (solid, remove dead copper, pour order 7): 4.064,140.97 4.445,141.351 147.828,141.351 147.828,0.889 146.939,0 2.54,0 2.54,139.7 3.81,140.97

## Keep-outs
Keep-Out Layer:
  the board outline again, w0.254

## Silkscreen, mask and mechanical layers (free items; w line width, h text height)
Top Overlay:
  text "AL3" at 65.913,18.288 h0.76 r90
  text "AL4" at 68.453,18.288 h0.76 r90
  text "AL7" at 70.993,18.288 h0.76 r90
  text "AL8" at 73.533,18.288 h0.76 r90
  text "AL11" at 75.946,18.288 h0.76 r90
  text "AL12" at 78.613,18.288 h0.76 r90
  text "AL15" at 81.153,18.288 h0.76 r90
  text "AL16" at 83.693,18.288 h0.76 r90
  text "MOSI" at 44.577,17.78 h0.76 r90
  text "MOSI" at 117.729,17.78 h0.76 r90
  text "GND" at 31.877,17.653 h0.76 r90
  text "SCK" at 34.417,17.653 h0.76 r90
  text "GND" at 36.957,17.653 h0.76 r90
  text "MISO" at 39.497,17.653 h0.76 r90
  text "GND" at 42.037,17.653 h0.76 r90
  text "3V3" at 47.117,17.653 h0.76 r90
  text "GND" at 105.029,17.653 h0.76 r90
  text "SCK" at 107.569,17.653 h0.76 r90
  text "GND" at 110.109,17.653 h0.76 r90
  text "MISO" at 112.649,17.653 h0.76 r90
  text "GND" at 115.189,17.653 h0.76 r90
  text "3V3" at 120.269,17.653 h0.76 r90
  text "B1" at 39.497,15.113 h0.76 r90
  text "AL1" at 65.913,15.113 h0.76 r90
  text "AL2" at 68.453,15.113 h0.76 r90
  text "AL5" at 70.993,15.113 h0.76 r90
  text "AL6" at 73.533,15.113 h0.76 r90
  text "AL9" at 75.946,15.113 h0.76 r90
  text "AL10" at 78.613,15.113 h0.76 r90
  text "AL13" at 81.153,15.113 h0.76 r90
  text "AL14" at 83.693,15.113 h0.76 r90
  text "B2" at 112.649,15.113 h0.76 r90
  text "GND" at 31.877,14.986 h0.76 r90
  text "C1" at 34.417,14.986 h0.76 r90
  text "GND" at 36.957,14.986 h0.76 r90
  text "GND" at 42.037,14.986 h0.76 r90
  text "A1" at 44.577,14.986 h0.76 r90
  text "3V3" at 47.117,14.986 h0.76 r90
  text "GND" at 105.029,14.986 h0.76 r90
  text "C2" at 107.569,14.986 h0.76 r90
  text "GND" at 110.109,14.986 h0.76 r90
  text "GND" at 115.189,14.986 h0.76 r90
  text "A2" at 117.729,14.986 h0.76 r90
  text "3V3" at 120.269,14.986 h0.76 r90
